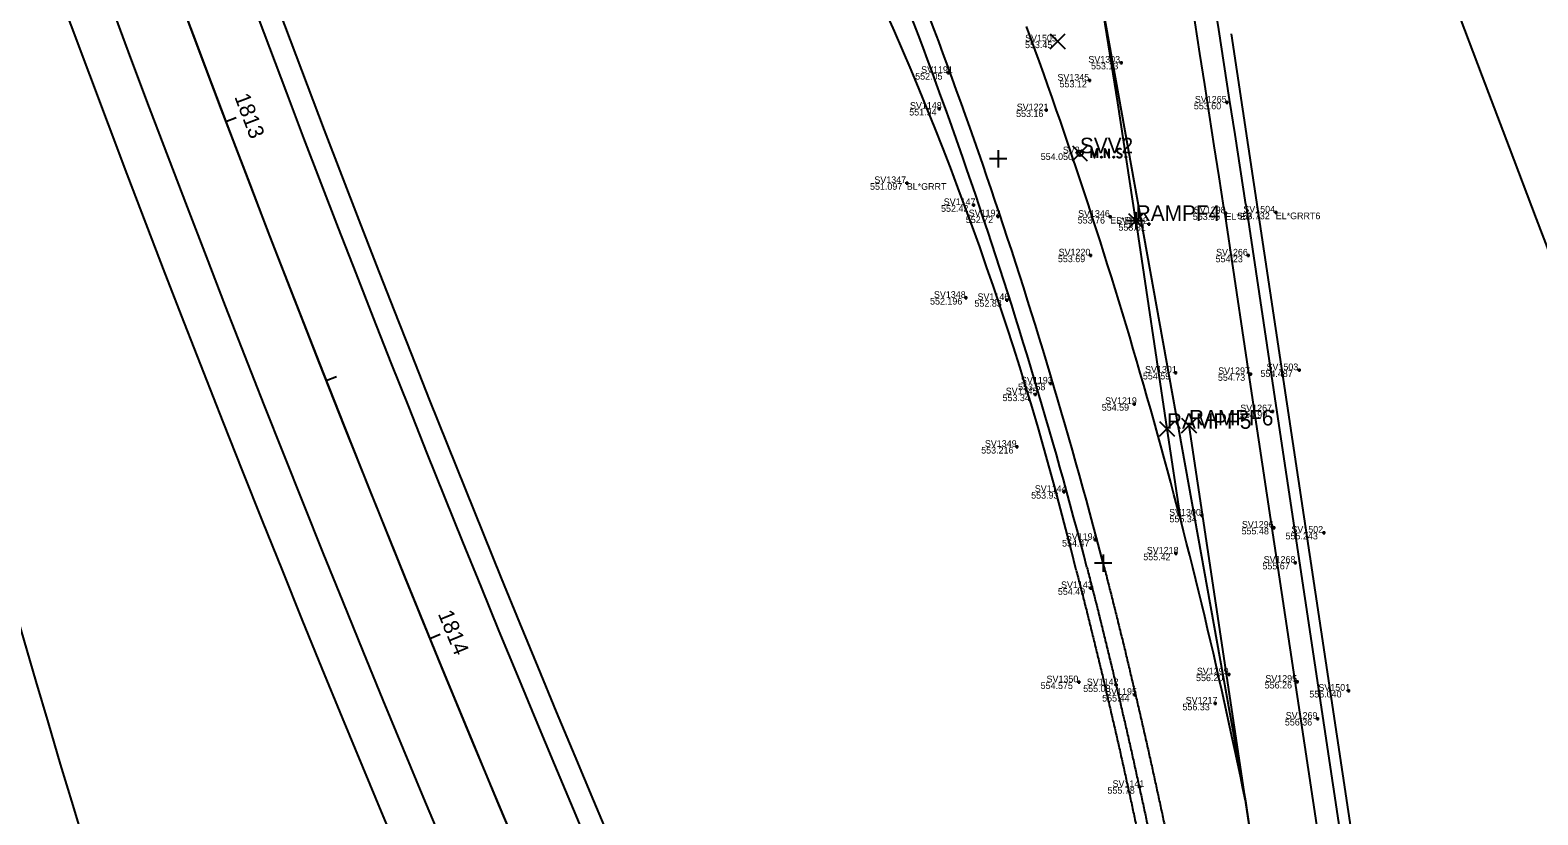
# Model space of a CAD drawing. Extents: x 6334 to 41599, y 9030 to 59113.
# Drawn here: x 20842.8 to 21114.1, y 34759.9 to 34901.1 of the extents above; entities that cross this region are included whole.
import ezdxf

# ---------------------------------------------------------------- set-up
doc = ezdxf.new("R2010")
doc.units = 0
for name, color, linetype in [('GE_X_CL_20', 7, 'Continuous'), ('GE_X_CL_50', 7, 'Continuous'), ('GK_Visualization', 7, 'Continuous'), ('PM_X_CL_Double_Solid', 7, 'Continuous'), ('PM_X_Lane_Line', 7, 'Continuous'), ('PV_X_EOP', 7, 'Continuous'), ('PV_X_Shoulder', 7, 'Continuous'), ('RD_X_GR_Lt', 7, 'Continuous'), ('RD_X_GR_Rt', 7, 'Continuous'), ('RW_X_Esmt_LA', 7, 'Continuous'), ('SV_P_Control_Cells_Set', 7, 'Continuous'), ('SV_X_Random_Point', 7, 'Continuous'), ('SV_X_Shot_Marker', 7, 'Continuous'), ('SV_X_Text_Comment', 7, 'Continuous'), ('SV_X_Text_Elevation', 7, 'Continuous'), ('SV_X_Text_Name', 7, 'Continuous')]:
    doc.layers.add(name, color=color, linetype=linetype)

msp = doc.modelspace()

# ---------------------------------------------------------------- linework, layer by layer
at = {"layer": 'GE_X_CL_20'}
for p, q in [((20878, 34884.69), (20879.87, 34885.4)), ((20896.06, 34838.06), (20897.92, 34838.8)), ((20914.71, 34791.67), (20916.56, 34792.43))]:
    msp.add_line(p, q, dxfattribs=at)
msp.add_arc((24529.94, 36271.9), 3906.53, 186.21667, 209.21667, dxfattribs=at)
at = {"layer": 'GE_X_CL_50'}
msp.add_arc((32581.78, 39251.96), 12277.67, 194.525, 202.716667, dxfattribs=at)
at = {"layer": 'GK_Visualization'}
for p, q in [((21030.35, 34877.62), (21033.01, 34880.29)), ((21030.35, 34880.29), (21033.01, 34877.62)), ((21018.53, 34877.96), (21015.41, 34877.96)), ((21016.97, 34879.52), (21016.97, 34876.4)), ((21043.28, 34866.8), (21040.16, 34866.8)), ((21040.39, 34865.47), (21043.06, 34868.14)), ((21040.39, 34868.14), (21043.06, 34865.47)), ((21041.72, 34868.36), (21041.72, 34865.24)), ((21041.72, 34866.8), (21047.34, 34829.39)), ((21049.96, 34828.65), (21052.63, 34831.32)), ((21049.96, 34831.32), (21052.63, 34828.65)), ((21046.01, 34828.06), (21048.68, 34830.73)), ((21046.01, 34830.73), (21048.68, 34828.06)), ((21047.34, 34829.39), (21049.79, 34813.1)), ((21051.3, 34829.99), (21084.27, 34610.45)), ((21051.3, 34829.99), (21084.27, 34610.45)), ((21037.4, 34805.21), (21034.28, 34805.21)), ((21037.4, 34805.21), (21034.28, 34805.21)), ((21035.84, 34806.77), (21035.84, 34803.65)), ((21035.84, 34806.77), (21035.84, 34803.65))]:
    msp.add_line(p, q, dxfattribs=at)
for centre, radius, start, end in [((28229.01, 37734.18), 7639.44, 189.175, 202.716667), ((28229.01, 37734.18), 7639.44, 189.175, 202.716667), ((32581.78, 39251.96), 12277.67, 194.525, 202.716667), ((32581.78, 39251.96), 12277.67, 194.525, 202.716667), ((24529.91, 36271.94), 3906.53, 186.21497, 209.2138), ((24529.91, 36271.94), 3906.53, 186.21497, 209.2138), ((24529.94, 36271.9), 3906.53, 186.21667, 209.21667), ((24529.94, 36271.9), 3906.53, 186.21667, 209.21667), ((17264.37, 34299.46), 3819.72, 8.54167, 15.41472), ((17264.37, 34299.46), 3819.72, 8.54167, 15.41472), ((20111.51, 34565.44), 954.93, 14.54167, 23.54167)]:
    msp.add_arc(centre, radius, start, end, dxfattribs=at)
msp.add_spline([(21035.84, 34805.21), (21036.52, 34802.59), (21037.19, 34799.97), (21037.85, 34797.35), (21038.5, 34794.73), (21039.15, 34792.11), (21039.79, 34789.48), (21040.42, 34786.85), (21041.04, 34784.22), (21041.66, 34781.59), (21042.28, 34778.96), (21042.88, 34776.33), (21043.48, 34773.69), (21044.08, 34771.05), (21044.66, 34768.42), (21045.24, 34765.78), (21045.82, 34763.13), (21046.39, 34760.49), (21046.95, 34757.85), (21047.51, 34755.21), (21048.06, 34752.56), (21048.61, 34749.91), (21049.15, 34747.26), (21049.69, 34744.62), (21050.22, 34741.97), (21050.75, 34739.31), (21051.27, 34736.66), (21051.78, 34734.01), (21052.29, 34731.36), (21052.8, 34728.7), (21053.3, 34726.05), (21053.8, 34723.39), (21054.3, 34720.73), (21054.78, 34718.07), (21055.27, 34715.42), (21055.75, 34712.76), (21056.23, 34710.1), (21056.7, 34707.43), (21057.17, 34704.77), (21057.64, 34702.11), (21058.1, 34699.45), (21058.56, 34696.78), (21059.01, 34694.12), (21059.46, 34691.46), (21059.91, 34688.79), (21060.36, 34686.12), (21060.8, 34683.46), (21061.24, 34680.79), (21061.68, 34678.12), (21062.11, 34675.46), (21062.55, 34672.79), (21062.98, 34670.12), (21063.4, 34667.45), (21063.83, 34664.78), (21064.25, 34662.11), (21064.67, 34659.44), (21065.09, 34656.77), (21065.51, 34654.1), (21065.92, 34651.43), (21066.34, 34648.76), (21066.75, 34646.09), (21067.16, 34643.42), (21067.57, 34640.75), (21067.98, 34638.08), (21068.38, 34635.4), (21068.79, 34632.73), (21069.2, 34630.06), (21069.6, 34627.39), (21070, 34624.72), (21070.41, 34622.04), (21070.81, 34619.37), (21071.21, 34616.7), (21071.61, 34614.03), (21072.01, 34611.35), (21072.42, 34608.68)], degree=3, dxfattribs=at)
at = {"layer": 'PM_X_CL_Double_Solid'}
for p, q in [((21035.74, 34905.29), (21061.45, 34762.43)), ((21061.45, 34762.43), (21084.27, 34610.45))]:
    msp.add_line(p, q, dxfattribs=at)
msp.add_arc((20125.43, 34573.33), 954.93, 11.42127, 20.11867, dxfattribs=at)
at = {"layer": 'PM_X_Lane_Line'}
for centre, radius, start, end in [((28229.01, 37734.18), 7639.44, 189.175, 202.716667), ((24529.94, 36271.9), 3906.53, 186.21667, 209.21667), ((24529.94, 36271.9), 3906.53, 191.33607, 209.21667)]:
    msp.add_arc(centre, radius, start, end, dxfattribs=at)
at = {"layer": 'PV_X_EOP'}
for p, q in [((21057.55, 34869.18), (21063.16, 34831.77)), ((21063.16, 34831.77), (21096.14, 34612.23))]:
    msp.add_line(p, q, dxfattribs=at)
for centre, radius, start, end in [((28229.01, 37734.18), 7627.44, 191.807877, 202.716667), ((24529.94, 36271.9), 3918.53, 191.33607, 209.21667), ((24531.79, 36272.61), 3896.49, 192.87045, 209.21252), ((28229.01, 37734.18), 7651.44, 198.78578, 202.716667), ((17264.37, 34299.46), 3835.72, 8.54167, 13.90526), ((20111.51, 34565.44), 954.93, 14.54167, 23.54167)]:
    msp.add_arc(centre, radius, start, end, dxfattribs=at)
msp.add_spline([(21035.84, 34805.21), (21036.52, 34802.59), (21037.19, 34799.97), (21037.85, 34797.35), (21038.5, 34794.73), (21039.15, 34792.11), (21039.79, 34789.48), (21040.42, 34786.85), (21041.04, 34784.22), (21041.66, 34781.59), (21042.28, 34778.96), (21042.88, 34776.33), (21043.48, 34773.69), (21044.08, 34771.05), (21044.66, 34768.42), (21045.24, 34765.78), (21045.82, 34763.13), (21046.39, 34760.49), (21046.95, 34757.85), (21047.51, 34755.21), (21048.06, 34752.56), (21048.61, 34749.91), (21049.15, 34747.26), (21049.69, 34744.62), (21050.22, 34741.97), (21050.75, 34739.31), (21051.27, 34736.66), (21051.78, 34734.01), (21052.29, 34731.36), (21052.8, 34728.7), (21053.3, 34726.05), (21053.8, 34723.39), (21054.3, 34720.73), (21054.78, 34718.07), (21055.27, 34715.42), (21055.75, 34712.76), (21056.23, 34710.1), (21056.7, 34707.43), (21057.17, 34704.77), (21057.64, 34702.11), (21058.1, 34699.45), (21058.56, 34696.78), (21059.01, 34694.12), (21059.46, 34691.46), (21059.91, 34688.79), (21060.36, 34686.12), (21060.8, 34683.46), (21061.24, 34680.79), (21061.68, 34678.12), (21062.11, 34675.46), (21062.55, 34672.79), (21062.98, 34670.12), (21063.4, 34667.45), (21063.83, 34664.78), (21064.25, 34662.11), (21064.67, 34659.44), (21065.09, 34656.77), (21065.51, 34654.1), (21065.92, 34651.43), (21066.34, 34648.76), (21066.75, 34646.09), (21067.16, 34643.42), (21067.57, 34640.75), (21067.98, 34638.08), (21068.38, 34635.4), (21068.79, 34632.73), (21069.2, 34630.06), (21069.6, 34627.39), (21070, 34624.72), (21070.41, 34622.04), (21070.81, 34619.37), (21071.21, 34616.7), (21071.61, 34614.03), (21072.01, 34611.35), (21072.42, 34608.68)], degree=3, dxfattribs=at)
at = {"layer": 'PV_X_Shoulder'}
for p, q in [((21061.5, 34869.77), (21067.12, 34832.37)), ((21067.12, 34832.37), (21100.09, 34612.83))]:
    msp.add_line(p, q, dxfattribs=at)
for centre, radius, start, end in [((28229.01, 37734.18), 7619.44, 191.815419, 202.716667), ((24529.94, 36271.9), 3926.53, 191.34141, 209.21667), ((24529.94, 36271.9), 3890.53, 192.86631, 209.21667), ((17264.37, 34299.46), 3839.72, 8.54167, 14.61747), ((28229.01, 37734.18), 7655.44, 198.78578, 202.716667), ((20111.51, 34565.44), 951.93, 14.54167, 23.54167)]:
    msp.add_arc(centre, radius, start, end, dxfattribs=at)
msp.add_spline([(21032.94, 34804.46), (21033.61, 34801.85), (21034.28, 34799.24), (21034.94, 34796.62), (21035.59, 34794.01), (21036.23, 34791.39), (21036.87, 34788.77), (21037.5, 34786.15), (21038.12, 34783.53), (21038.74, 34780.91), (21039.35, 34778.28), (21039.96, 34775.66), (21040.56, 34773.03), (21041.15, 34770.4), (21041.73, 34767.77), (21042.31, 34765.13), (21042.89, 34762.5), (21043.46, 34759.86), (21044.02, 34757.23), (21044.57, 34754.59), (21045.13, 34751.95), (21045.67, 34749.31), (21046.21, 34746.67), (21046.75, 34744.02), (21047.28, 34741.38), (21047.8, 34738.73), (21048.32, 34736.09), (21048.84, 34733.44), (21049.35, 34730.79), (21049.85, 34728.14), (21050.36, 34725.49), (21050.85, 34722.84), (21051.35, 34720.19), (21051.83, 34717.53), (21052.32, 34714.88), (21052.8, 34712.22), (21053.27, 34709.57), (21053.75, 34706.91), (21054.22, 34704.25), (21054.68, 34701.6), (21055.14, 34698.94), (21055.6, 34696.28), (21056.05, 34693.62), (21056.51, 34690.96), (21056.95, 34688.29), (21057.4, 34685.63), (21057.84, 34682.97), (21058.28, 34680.3), (21058.72, 34677.64), (21059.15, 34674.98), (21059.58, 34672.31), (21060.01, 34669.65), (21060.44, 34666.98), (21060.87, 34664.31), (21061.29, 34661.65), (21061.71, 34658.98), (21062.13, 34656.31), (21062.54, 34653.64), (21062.96, 34650.97), (21063.37, 34648.3), (21063.78, 34645.63), (21064.19, 34642.96), (21064.6, 34640.29), (21065.01, 34637.62), (21065.42, 34634.95), (21065.82, 34632.28), (21066.23, 34629.61), (21066.63, 34626.94), (21067.04, 34624.27), (21067.44, 34621.6), (21067.84, 34618.92), (21068.24, 34616.25), (21068.65, 34613.58), (21069.05, 34610.91), (21069.45, 34608.23)], degree=3, dxfattribs=at)
at = {"layer": 'RD_X_GR_Lt'}
msp.add_line((21058.92, 34900.43), (21102.07, 34613.12), dxfattribs=at)
at = {"layer": 'RD_X_GR_Rt'}
msp.add_arc((20454.02, 34663.41), 593.86, 13.68967, 25.4108, dxfattribs=at)
msp.add_spline([(21031, 34803.96), (21031.68, 34801.35), (21032.34, 34798.74), (21033, 34796.14), (21033.65, 34793.53), (21034.29, 34790.92), (21034.93, 34788.3), (21035.56, 34785.69), (21036.18, 34783.07), (21036.79, 34780.45), (21037.4, 34777.83), (21038.01, 34775.21), (21038.61, 34772.59), (21039.2, 34769.96), (21039.78, 34767.33), (21040.36, 34764.71), (21040.93, 34762.08), (21041.5, 34759.44), (21042.06, 34756.81), (21042.62, 34754.18), (21043.17, 34751.54), (21043.71, 34748.91), (21044.25, 34746.27), (21044.79, 34743.63), (21045.32, 34740.99), (21045.84, 34738.35), (21046.36, 34735.7), (21046.87, 34733.06), (21047.38, 34730.41), (21047.89, 34727.77), (21048.39, 34725.12), (21048.89, 34722.47), (21049.38, 34719.82), (21049.87, 34717.17), (21050.35, 34714.52), (21050.83, 34711.87), (21051.31, 34709.22), (21051.78, 34706.56), (21052.25, 34703.91), (21052.71, 34701.25), (21053.17, 34698.6), (21053.63, 34695.94), (21054.08, 34693.28), (21054.53, 34690.62), (21054.98, 34687.96), (21055.43, 34685.3), (21055.87, 34682.64), (21056.31, 34679.98), (21056.74, 34677.32), (21057.18, 34674.66), (21057.61, 34671.99), (21058.04, 34669.33), (21058.47, 34666.66), (21058.89, 34664), (21059.31, 34661.33), (21059.73, 34658.67), (21060.15, 34656), (21060.57, 34653.33), (21060.98, 34650.67), (21061.4, 34648), (21061.81, 34645.33), (21062.22, 34642.66), (21062.63, 34639.99), (21063.03, 34637.32), (21063.44, 34634.65), (21063.85, 34631.98), (21064.25, 34629.31), (21064.66, 34626.64), (21065.06, 34623.97), (21065.46, 34621.3), (21065.86, 34618.63), (21066.27, 34615.95), (21066.67, 34613.28), (21067.07, 34610.61), (21067.47, 34607.94)], degree=3, dxfattribs=at)
at = {"layer": 'RW_X_Esmt_LA'}
msp.add_arc((23569.82, 35580.33), 2839.93, 195.3477, 205.35619, dxfattribs=at)
at = {"layer": 'SV_P_Control_Cells_Set'}
for points in [[(21033.77, 34878.16), (21033.77, 34879.76), (21034.28, 34878.16), (21034.76, 34879.76), (21034.76, 34878.16)], [(21035.53, 34878.37), (21035.59, 34878.37), (21035.62, 34878.35), (21035.65, 34878.3), (21035.65, 34878.23), (21035.62, 34878.18), (21035.59, 34878.16), (21035.53, 34878.16), (21035.5, 34878.18), (21035.47, 34878.23), (21035.47, 34878.3), (21035.5, 34878.35), (21035.53, 34878.37)], [(21036.14, 34878.16), (21036.14, 34879.76), (21036.97, 34878.16), (21036.97, 34879.76)], [(21037.75, 34878.37), (21037.8, 34878.37), (21037.84, 34878.35), (21037.87, 34878.3), (21037.87, 34878.23), (21037.84, 34878.18), (21037.8, 34878.16), (21037.75, 34878.16), (21037.72, 34878.18), (21037.68, 34878.23), (21037.68, 34878.3), (21037.72, 34878.35), (21037.75, 34878.37)], [(21039.12, 34879.64), (21039.09, 34879.67), (21039.06, 34879.69), (21038.96, 34879.73), (21038.84, 34879.76), (21038.75, 34879.76), (21038.72, 34879.76), (21038.58, 34879.72), (21038.45, 34879.64), (21038.38, 34879.54), (21038.35, 34879.44), (21038.35, 34879.37), (21038.38, 34879.27), (21038.47, 34879.18), (21039.07, 34878.8), (21039.13, 34878.75), (21039.15, 34878.7), (21039.17, 34878.62), (21039.17, 34878.55), (21039.16, 34878.47), (21039.15, 34878.42), (21039.13, 34878.36), (21039.1, 34878.31), (21039.08, 34878.27), (21039.05, 34878.23), (21039.02, 34878.21), (21038.97, 34878.18), (21038.94, 34878.17), (21038.84, 34878.16), (21038.69, 34878.16), (21038.59, 34878.18), (21038.44, 34878.27), (21038.35, 34878.35)], [(21039.93, 34878.37), (21039.99, 34878.37), (21040.02, 34878.35), (21040.05, 34878.3), (21040.05, 34878.23), (21040.02, 34878.18), (21039.99, 34878.16), (21039.93, 34878.16), (21039.9, 34878.18), (21039.87, 34878.23), (21039.87, 34878.3), (21039.9, 34878.35), (21039.93, 34878.37)]]:
    msp.add_lwpolyline(points, dxfattribs=at)
msp.add_circle((21031.68, 34878.96), 0.497, dxfattribs=at)
at = {"layer": 'SV_X_Random_Point'}
for p, q in [((21026.35, 34897.75), (21029.01, 34900.42)), ((21026.35, 34900.42), (21029.01, 34897.75))]:
    msp.add_line(p, q, dxfattribs=at)
at = {"layer": 'SV_X_Shot_Marker'}
for p, q in [((21007.98, 34893.71), (21007.98, 34893.11)), ((21039.38, 34895.26), (21038.78, 34895.26)), ((21039.08, 34895.56), (21039.08, 34894.96)), ((21008.28, 34893.41), (21007.68, 34893.41)), ((21033.7, 34892.03), (21033.1, 34892.03)), ((21033.4, 34892.33), (21033.4, 34891.73)), ((21058.11, 34888.37), (21058.11, 34887.77)), ((21006.64, 34886.96), (21006.04, 34886.96)), ((21006.34, 34887.26), (21006.34, 34886.66)), ((21025.9, 34886.69), (21025.3, 34886.69)), ((21025.6, 34886.99), (21025.6, 34886.39)), ((21058.41, 34888.07), (21057.81, 34888.07)), ((21000.83, 34873.59), (21000.23, 34873.59)), ((21000.53, 34873.89), (21000.53, 34873.29)), ((21012.82, 34869.63), (21012.22, 34869.63)), ((21012.52, 34869.93), (21012.52, 34869.33)), ((21017.24, 34867.61), (21016.64, 34867.61)), ((21016.94, 34867.91), (21016.94, 34867.31)), ((21037.43, 34867.52), (21036.83, 34867.52)), ((21037.13, 34867.82), (21037.13, 34867.22)), ((21044.06, 34866.53), (21044.06, 34865.93)), ((21058.17, 34868.17), (21057.57, 34868.17)), ((21057.87, 34868.47), (21057.87, 34867.87)), ((21067.21, 34868.3), (21066.61, 34868.3)), ((21066.91, 34868.6), (21066.91, 34868)), ((21044.36, 34866.23), (21043.76, 34866.23)), ((21033.9, 34860.57), (21033.3, 34860.57)), ((21033.6, 34860.87), (21033.6, 34860.27)), ((21062.23, 34860.56), (21061.63, 34860.56)), ((21061.93, 34860.86), (21061.93, 34860.26)), ((21011.14, 34853.24), (21011.14, 34852.64)), ((21011.44, 34852.94), (21010.84, 34852.94)), ((21018.85, 34852.55), (21018.25, 34852.55)), ((21018.55, 34852.85), (21018.55, 34852.25)), ((21049.16, 34839.47), (21048.56, 34839.47)), ((21048.86, 34839.77), (21048.86, 34839.17)), ((21062.36, 34839.53), (21062.36, 34838.93)), ((21071.42, 34839.93), (21070.82, 34839.93)), ((21071.12, 34840.23), (21071.12, 34839.63)), ((21026.67, 34837.53), (21026.07, 34837.53)), ((21026.37, 34837.83), (21026.37, 34837.23)), ((21062.66, 34839.23), (21062.06, 34839.23)), ((21023.92, 34835.57), (21023.32, 34835.57)), ((21023.62, 34835.87), (21023.62, 34835.27)), ((21041.46, 34834.14), (21041.46, 34833.54)), ((21041.76, 34833.84), (21041.16, 34833.84)), ((21066.63, 34832.53), (21066.03, 34832.53)), ((21066.33, 34832.83), (21066.33, 34832.23)), ((21020.64, 34826.14), (21020.04, 34826.14)), ((21020.34, 34826.44), (21020.34, 34825.84)), ((21029.11, 34818.02), (21028.51, 34818.02)), ((21028.81, 34818.32), (21028.81, 34817.72)), ((21053.94, 34813.77), (21053.34, 34813.77)), ((21053.64, 34814.07), (21053.64, 34813.47)), ((21034.4, 34809.7), (21034.4, 34809.1)), ((21066.88, 34811.59), (21066.28, 34811.59)), ((21066.58, 34811.89), (21066.58, 34811.29)), ((21075.87, 34810.69), (21075.27, 34810.69)), ((21075.57, 34810.99), (21075.57, 34810.39)), ((21034.7, 34809.4), (21034.1, 34809.4)), ((21049.22, 34806.94), (21048.62, 34806.94)), ((21048.92, 34807.24), (21048.92, 34806.64)), ((21070.73, 34805.29), (21070.13, 34805.29)), ((21070.43, 34805.59), (21070.43, 34804.99)), ((21033.87, 34800.72), (21033.27, 34800.72)), ((21033.57, 34801.02), (21033.57, 34800.42)), ((21058.76, 34785.19), (21058.16, 34785.19)), ((21058.46, 34785.49), (21058.46, 34784.89)), ((21031.79, 34783.78), (21031.19, 34783.78)), ((21031.49, 34784.08), (21031.49, 34783.48)), ((21038.48, 34783.25), (21037.88, 34783.25)), ((21038.18, 34783.55), (21038.18, 34782.95)), ((21071.08, 34783.87), (21070.48, 34783.87)), ((21070.78, 34784.17), (21070.78, 34783.57)), ((21080.02, 34782.55), (21080.02, 34781.95)), ((21041.81, 34781.52), (21041.21, 34781.52)), ((21041.51, 34781.82), (21041.51, 34781.22)), ((21056.32, 34779.95), (21055.72, 34779.95)), ((21056.02, 34780.25), (21056.02, 34779.65)), ((21080.32, 34782.25), (21079.72, 34782.25)), ((21074.75, 34777.21), (21074.15, 34777.21)), ((21074.45, 34777.51), (21074.45, 34776.91)), ((21042.72, 34764.94), (21042.12, 34764.94)), ((21042.42, 34765.24), (21042.42, 34764.64))]:
    msp.add_line(p, q, dxfattribs=at)

# ---------------------------------------------------------------- texts
at = {"layer": 'GE_X_CL_20'}
for s, rotation, p in [('1813', 290.7996, (20879.52, 34889.13)), ('1814', 292.2662, (20916.13, 34796.11))]:
    msp.add_text(s, height=2.8, rotation=rotation, dxfattribs=at).set_placement(p)
at = {"layer": 'GK_Visualization'}
for s, p in [('SVV2', (21031.68, 34878.96)), ('RAMPF4', (21041.72, 34866.8)), ('RAMPF5', (21047.34, 34829.39)), ('RAMPF6', (21051.3, 34829.99))]:
    msp.add_text(s, height=2.8, dxfattribs=at).set_placement(p)
at = {"layer": 'SV_X_Text_Comment'}
for s, p in [('BL*GRRT', (21000.53, 34872.39)), ('EL*EB', (21037.13, 34866.32)), ('EL*EP', (21057.87, 34866.97)), ('EL*GRRT6', (21066.91, 34867.1))]:
    msp.add_text(s, height=1.2, dxfattribs=at).set_placement(p)
at = {"layer": 'SV_X_Text_Elevation'}
for s, p in [('553.45', (21021.8, 34897.88)), ('553.13', (21033.68, 34894.06)), ('552.05', (21002.04, 34892.21)), ('553.12', (21028.02, 34890.83)), ('551.94', (21000.97, 34885.76)), ('553.16', (21020.2, 34885.49)), ('553.60', (21052.18, 34886.87)), ('554.050', (21024.63, 34877.76)), ('551.097', (20993.92, 34872.39)), ('552.42', (21006.7, 34868.43)), ('552.72', (21011.15, 34866.41)), ('553.76', (21031.28, 34866.32)), ('553.95', (21051.99, 34866.97)), ('553.732', (21060.03, 34867.1)), ('553.81', (21038.61, 34865.03)), ('553.69', (21027.72, 34859.37)), ('554.23', (21056.08, 34859.36)), ('552.196', (21004.72, 34851.74)), ('552.83', (21012.71, 34851.35)), ('554.59', (21043.01, 34838.27)), ('554.487', (21064.16, 34838.73)), ('553.58', (21020.55, 34836.33)), ('554.73', (21056.51, 34838.03)), ('553.34', (21017.76, 34834.37)), ('554.59', (21035.61, 34832.64)), ('554.99', (21060.46, 34831.33)), ('553.216', (21013.92, 34824.94)), ('553.93', (21022.91, 34816.82)), ('555.34', (21047.8, 34812.57)), ('555.48', (21060.77, 34810.39)), ('555.243', (21068.68, 34809.49)), ('554.47', (21028.47, 34808.2)), ('555.42', (21043.08, 34805.74)), ('555.67', (21064.51, 34804.09)), ('554.49', (21027.71, 34799.52)), ('556.20', (21052.57, 34783.99)), ('554.575', (21024.61, 34782.58)), ('555.08', (21032.27, 34782.05)), ('556.26', (21064.93, 34782.67)), ('555.44', (21035.68, 34780.32)), ('556.33', (21050.13, 34778.75)), ('556.040', (21072.95, 34781.05)), ('556.36', (21068.55, 34776.01)), ('555.78', (21036.64, 34763.74))]:
    msp.add_text(s, height=1.2, dxfattribs=at).set_placement(p)
at = {"layer": 'SV_X_Text_Name'}
for s, p in [('SV1505', (21021.82, 34899.08)), ('SV1303', (21033.2, 34895.26)), ('SV1191', (21003.11, 34893.41)), ('SV1345', (21027.63, 34892.03)), ('SV1265', (21052.36, 34888.07)), ('SV1148', (21001.11, 34886.96)), ('SV1221', (21020.31, 34886.69)), ('SV2', (21028.6, 34878.96)), ('SV1347', (20994.7, 34873.59)), ('SV1147', (21007.18, 34869.63)), ('SV1298', (21052.18, 34868.17)), ('SV1504', (21061.08, 34868.3)), ('SV1192', (21011.67, 34867.61)), ('SV1346', (21031.35, 34867.52)), ('SV1302', (21038.2, 34866.23)), ('SV1220', (21027.85, 34860.57)), ('SV1266', (21056.18, 34860.56)), ('SV1348', (21005.42, 34852.94)), ('SV1146', (21013.26, 34852.55)), ('SV1301', (21043.4, 34839.47)), ('SV1297', (21056.56, 34839.23)), ('SV1503', (21065.25, 34839.93)), ('SV1145', (21018.34, 34835.57)), ('SV1193', (21021.07, 34837.53)), ('SV1219', (21036.21, 34833.84)), ('SV1267', (21060.53, 34832.53)), ('SV1349', (21014.58, 34826.14)), ('SV1144', (21023.56, 34818.02)), ('SV1300', (21047.73, 34813.77)), ('SV1296', (21060.82, 34811.59)), ('SV1194', (21029.14, 34809.4)), ('SV1502', (21069.73, 34810.69)), ('SV1218', (21043.71, 34806.94)), ('SV1268', (21064.74, 34805.29)), ('SV1143', (21028.28, 34800.72)), ('SV1299', (21052.72, 34785.19)), ('SV1350', (21025.68, 34783.78)), ('SV1142', (21032.92, 34783.25)), ('SV1195', (21036.22, 34781.52)), ('SV1295', (21065.04, 34783.87)), ('SV1501', (21074.58, 34782.25)), ('SV1217', (21050.71, 34779.95)), ('SV1269', (21068.71, 34777.21)), ('SV1141', (21037.56, 34764.94))]:
    msp.add_text(s, height=1.2, dxfattribs=at).set_placement(p)

doc.saveas('drawing.dxf')
